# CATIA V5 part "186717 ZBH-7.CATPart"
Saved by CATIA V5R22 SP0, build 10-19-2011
Part number: 186717 ZBH-7
Property "ParasolidId": 30
Property "PSOL_INSTNR": 10
Property "ParasolidId": 27
Property "PSOL_INSTNR": 10
Bounding box of the stored display mesh (mm): x 0 to 3, y -3.329 to 3.329, z -3.5 to 3.5
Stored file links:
  U:\S9A\PER\CAO\Assemblage\Cadre\Chariot_Y\Prehenseur\186717 ZBH-7.CATPart
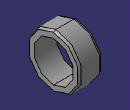
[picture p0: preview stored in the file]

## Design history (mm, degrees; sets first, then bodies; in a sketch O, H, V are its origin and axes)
Body1 "186717 ZBH-7" (main body)
  Solid1: solid without history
